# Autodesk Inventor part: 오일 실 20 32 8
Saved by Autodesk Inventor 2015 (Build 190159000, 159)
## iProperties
Created: 2024-12
Part Number: 오일 실 20 32 8
Material: 일반
Document SubType Name: Modeling
Designer: 102-5
Density: 1 g/cm^3
Appearance: 기본값
Author: 102-5
Author: jhkim
Description: 오일-실
Creation Date: 2024-11-28
Sending System: Autodesk Inventor 2025
Preprocessor: ST-DEVELOPER v20
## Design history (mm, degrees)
node "오일 실 20 32 81"
body "Solid1"
node "기준1"
